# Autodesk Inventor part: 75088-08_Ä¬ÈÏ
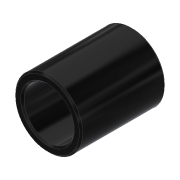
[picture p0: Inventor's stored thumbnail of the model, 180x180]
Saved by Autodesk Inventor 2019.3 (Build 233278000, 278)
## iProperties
Created: 2010-06
Part Number: 75088-08_Ä¬ÈÏ
Material: Ogólny
Document SubType Name: Modeling
Designer: CADENGINEERING4
Density: 1 g/cm^3
Appearance: Gładki — czarny
Author: CADENGINEERING4
Revision Number: ÈÎºÎ
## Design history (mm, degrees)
feature "NONE"
node "Bryła1"
